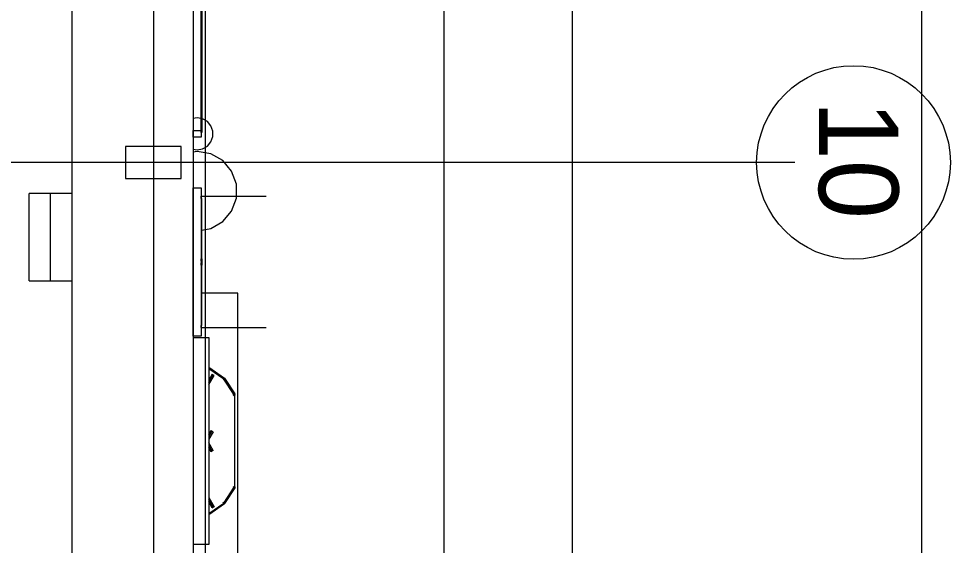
# Model space of a CAD drawing. Extents: x -264165 to -263575, y -1242333 to -1242036.
# Drawn here: x -263797.23 to -263785.53, y -1242144.69 to -1242138.07 of the extents above; entities that cross this region are included whole.
import ezdxf

# ---------------------------------------------------------------- set-up
doc = ezdxf.new("R2010")
doc.units = 0
doc.layers.add('KFA_HESCON_OSI_STAVBY', color=7, linetype='Continuous')
doc.layers.add('KFA_SITUACIA_DRS_VYTYCOVAK_SEDA', color=7, linetype='Continuous')

msp = doc.modelspace()

# ---------------------------------------------------------------- linework, layer by layer
at = {"layer": 'KFA_HESCON_OSI_STAVBY'}
for p, q in [((-263795.543, -1242080.447), (-263795.543, -1242248.737)), ((-263787.486, -1242139.882), (-263921.823, -1242139.882)), ((-263787.486, -1242139.882), (-263787.486, -1242139.882))]:
    msp.add_line(p, q, dxfattribs=at)
msp.add_circle((-263786.751, -1242139.882), 1.216, dxfattribs=at)
at = {"layer": 'KFA_SITUACIA_DRS_VYTYCOVAK_SEDA'}
for p, q in [((-263785.893, -1242228.625), (-263785.893, -1242090.308)), ((-263791.893, -1242228.625), (-263791.893, -1242100.14)), ((-263790.279, -1242228.625), (-263790.279, -1242100.14)), ((-263794.893, -1242101.382), (-263794.893, -1242227.382)), ((-263796.568, -1242132.882), (-263796.568, -1242139.882)), ((-263796.568, -1242132.882), (-263796.568, -1242139.882)), ((-263795.043, -1242132.882), (-263795.043, -1242139.882)), ((-263795.043, -1242132.882), (-263795.043, -1242139.882)), ((-263795.043, -1242137.469), (-263795.043, -1242139.482)), ((-263795.043, -1242137.469), (-263795.043, -1242139.482)), ((-263794.943, -1242139.505), (-263794.943, -1242137.469)), ((-263794.943, -1242139.505), (-263794.943, -1242137.469)), ((-263794.933, -1242137.446), (-263794.933, -1242139.505)), ((-263794.933, -1242137.446), (-263794.933, -1242139.505)), ((-263794.993, -1242139.322), (-263795.043, -1242139.331)), ((-263794.993, -1242139.322), (-263795.043, -1242139.331)), ((-263794.943, -1242139.331), (-263794.993, -1242139.322)), ((-263794.943, -1242139.331), (-263794.993, -1242139.322)), ((-263794.924, -1242139.334), (-263794.933, -1242139.333)), ((-263794.924, -1242139.334), (-263794.933, -1242139.333)), ((-263794.864, -1242139.369), (-263794.924, -1242139.334)), ((-263794.864, -1242139.369), (-263794.924, -1242139.334)), ((-263794.82, -1242139.422), (-263794.864, -1242139.369)), ((-263794.82, -1242139.422), (-263794.864, -1242139.369)), ((-263794.796, -1242139.487), (-263794.82, -1242139.422)), ((-263794.796, -1242139.487), (-263794.82, -1242139.422)), ((-263795.043, -1242139.562), (-263795.043, -1242139.482)), ((-263795.043, -1242139.562), (-263795.043, -1242139.482)), ((-263795.043, -1242139.482), (-263794.943, -1242139.482)), ((-263795.043, -1242139.482), (-263794.943, -1242139.482)), ((-263795.043, -1242139.562), (-263795.043, -1242139.582)), ((-263795.043, -1242139.562), (-263795.043, -1242139.582)), ((-263794.943, -1242139.562), (-263795.043, -1242139.562)), ((-263794.943, -1242139.562), (-263795.043, -1242139.562)), ((-263795.043, -1242139.582), (-263795.043, -1242140.182)), ((-263795.043, -1242139.582), (-263795.043, -1242140.182)), ((-263794.943, -1242139.482), (-263794.943, -1242139.562)), ((-263794.943, -1242139.482), (-263794.943, -1242139.562)), ((-263794.933, -1242139.505), (-263794.943, -1242139.505)), ((-263794.933, -1242139.505), (-263794.943, -1242139.505)), ((-263794.82, -1242139.622), (-263794.796, -1242139.557)), ((-263794.82, -1242139.622), (-263794.796, -1242139.557)), ((-263794.796, -1242139.557), (-263794.796, -1242139.487)), ((-263794.796, -1242139.557), (-263794.796, -1242139.487)), ((-263795.193, -1242139.682), (-263795.893, -1242139.682)), ((-263795.193, -1242139.682), (-263795.893, -1242139.682)), ((-263795.893, -1242139.682), (-263795.893, -1242139.882)), ((-263795.893, -1242139.682), (-263795.893, -1242139.882)), ((-263795.193, -1242139.882), (-263795.193, -1242139.682)), ((-263795.193, -1242139.882), (-263795.193, -1242139.682)), ((-263795.193, -1242139.882), (-263795.193, -1242139.682)), ((-263795.193, -1242139.882), (-263795.193, -1242139.682)), ((-263794.924, -1242139.71), (-263794.864, -1242139.675)), ((-263794.924, -1242139.71), (-263794.864, -1242139.675)), ((-263794.864, -1242139.675), (-263794.82, -1242139.622)), ((-263794.864, -1242139.675), (-263794.82, -1242139.622)), ((-263795.043, -1242139.713), (-263794.993, -1242139.722)), ((-263795.043, -1242139.713), (-263794.993, -1242139.722)), ((-263794.993, -1242139.742), (-263795.043, -1242139.751)), ((-263794.993, -1242139.742), (-263795.043, -1242139.751)), ((-263794.993, -1242139.722), (-263794.924, -1242139.71)), ((-263794.993, -1242139.722), (-263794.924, -1242139.71)), ((-263794.822, -1242139.772), (-263794.993, -1242139.742)), ((-263794.822, -1242139.772), (-263794.993, -1242139.742)), ((-263794.671, -1242139.859), (-263794.822, -1242139.772)), ((-263794.671, -1242139.859), (-263794.822, -1242139.772)), ((-263796.568, -1242139.882), (-263796.568, -1242146.882)), ((-263796.568, -1242139.882), (-263796.568, -1242146.882)), ((-263795.893, -1242139.882), (-263795.893, -1242140.082)), ((-263795.893, -1242139.882), (-263795.893, -1242140.082)), ((-263795.193, -1242140.082), (-263795.193, -1242139.882)), ((-263795.193, -1242140.082), (-263795.193, -1242139.882)), ((-263795.193, -1242140.082), (-263795.193, -1242139.882)), ((-263795.193, -1242140.082), (-263795.193, -1242139.882)), ((-263795.043, -1242139.882), (-263795.043, -1242146.882)), ((-263795.043, -1242139.882), (-263795.043, -1242146.882)), ((-263794.56, -1242139.992), (-263794.671, -1242139.859)), ((-263794.56, -1242139.992), (-263794.671, -1242139.859)), ((-263794.5, -1242140.155), (-263794.56, -1242139.992)), ((-263794.5, -1242140.155), (-263794.56, -1242139.992)), ((-263795.893, -1242140.082), (-263795.193, -1242140.082)), ((-263795.893, -1242140.082), (-263795.193, -1242140.082)), ((-263794.5, -1242140.329), (-263794.5, -1242140.155)), ((-263794.5, -1242140.329), (-263794.5, -1242140.155)), ((-263797.101, -1242141.369), (-263797.101, -1242140.27)), ((-263797.101, -1242141.369), (-263797.101, -1242140.27)), ((-263796.834, -1242140.27), (-263797.101, -1242140.27)), ((-263796.834, -1242140.27), (-263797.101, -1242140.27)), ((-263796.834, -1242141.369), (-263796.834, -1242140.27)), ((-263796.834, -1242141.369), (-263796.834, -1242140.27)), ((-263796.568, -1242140.27), (-263796.834, -1242140.27)), ((-263796.568, -1242140.27), (-263796.834, -1242140.27)), ((-263795.043, -1242140.182), (-263795.043, -1242140.202)), ((-263795.043, -1242140.182), (-263795.043, -1242140.202)), ((-263795.043, -1242142.062), (-263795.043, -1242140.202)), ((-263795.043, -1242142.062), (-263795.043, -1242140.202)), ((-263795.043, -1242140.202), (-263794.943, -1242140.202)), ((-263795.043, -1242140.202), (-263794.943, -1242140.202)), ((-263794.943, -1242140.202), (-263794.943, -1242142.062)), ((-263794.943, -1242140.202), (-263794.943, -1242142.062)), ((-263794.943, -1242140.307), (-263794.128, -1242140.307)), ((-263794.943, -1242140.307), (-263794.128, -1242140.307)), ((-263794.943, -1242140.333), (-263794.943, -1242140.307)), ((-263794.943, -1242140.333), (-263794.943, -1242140.307)), ((-263794.943, -1242140.333), (-263794.933, -1242140.333)), ((-263794.943, -1242140.333), (-263794.933, -1242140.333)), ((-263794.933, -1242141.092), (-263794.933, -1242140.333)), ((-263794.933, -1242141.092), (-263794.933, -1242140.333)), ((-263794.56, -1242140.492), (-263794.5, -1242140.329)), ((-263794.56, -1242140.492), (-263794.5, -1242140.329)), ((-263794.671, -1242140.625), (-263794.56, -1242140.492)), ((-263794.671, -1242140.625), (-263794.56, -1242140.492)), ((-263794.822, -1242140.712), (-263794.671, -1242140.625)), ((-263794.822, -1242140.712), (-263794.671, -1242140.625)), ((-263794.933, -1242140.732), (-263794.822, -1242140.712)), ((-263794.933, -1242140.732), (-263794.822, -1242140.712)), ((-263794.943, -1242141.092), (-263794.933, -1242141.092)), ((-263794.943, -1242141.092), (-263794.933, -1242141.092)), ((-263794.943, -1242141.122), (-263794.943, -1242141.092)), ((-263794.943, -1242141.122), (-263794.943, -1242141.092)), ((-263794.943, -1242141.092), (-263794.933, -1242141.092)), ((-263794.943, -1242141.092), (-263794.933, -1242141.092)), ((-263794.933, -1242141.092), (-263794.933, -1242141.172)), ((-263794.933, -1242141.092), (-263794.933, -1242141.172)), ((-263794.943, -1242141.173), (-263794.943, -1242141.142)), ((-263794.943, -1242141.173), (-263794.943, -1242141.142)), ((-263794.933, -1242141.172), (-263794.943, -1242141.172)), ((-263794.933, -1242141.172), (-263794.943, -1242141.172)), ((-263794.933, -1242141.173), (-263794.943, -1242141.173)), ((-263794.933, -1242141.173), (-263794.943, -1242141.173)), ((-263794.933, -1242141.932), (-263794.933, -1242141.173)), ((-263794.933, -1242141.932), (-263794.933, -1242141.173)), ((-263797.101, -1242141.369), (-263796.834, -1242141.369)), ((-263797.101, -1242141.369), (-263796.834, -1242141.369)), ((-263796.834, -1242141.369), (-263796.568, -1242141.369)), ((-263796.834, -1242141.369), (-263796.568, -1242141.369)), ((-263794.482, -1242141.522), (-263794.933, -1242141.522)), ((-263794.482, -1242141.522), (-263794.933, -1242141.522)), ((-263794.482, -1242145.242), (-263794.482, -1242141.522)), ((-263794.482, -1242145.242), (-263794.482, -1242141.522)), ((-263794.943, -1242141.957), (-263794.943, -1242141.932)), ((-263794.943, -1242141.957), (-263794.943, -1242141.932)), ((-263794.933, -1242141.932), (-263794.943, -1242141.932)), ((-263794.933, -1242141.932), (-263794.943, -1242141.932)), ((-263794.943, -1242141.957), (-263794.128, -1242141.957)), ((-263794.943, -1242141.957), (-263794.128, -1242141.957)), ((-263795.043, -1242142.062), (-263795.043, -1242142.082)), ((-263795.043, -1242142.062), (-263795.043, -1242142.082)), ((-263794.943, -1242142.062), (-263795.043, -1242142.062)), ((-263794.943, -1242142.062), (-263795.043, -1242142.062)), ((-263795.043, -1242142.082), (-263794.847, -1242142.082)), ((-263795.043, -1242142.082), (-263794.847, -1242142.082)), ((-263794.847, -1242142.082), (-263794.847, -1242144.682)), ((-263794.847, -1242142.082), (-263794.847, -1242144.682)), ((-263794.847, -1242142.454), (-263794.649, -1242142.59)), ((-263794.847, -1242142.454), (-263794.649, -1242142.59)), ((-263794.656, -1242142.597), (-263794.847, -1242142.467)), ((-263794.656, -1242142.597), (-263794.847, -1242142.467)), ((-263794.656, -1242142.603), (-263794.847, -1242142.473)), ((-263794.656, -1242142.603), (-263794.847, -1242142.473)), ((-263794.847, -1242142.477), (-263794.842, -1242142.476)), ((-263794.847, -1242142.477), (-263794.842, -1242142.476)), ((-263794.842, -1242142.476), (-263794.842, -1242142.476)), ((-263794.842, -1242142.476), (-263794.842, -1242142.476)), ((-263794.804, -1242142.543), (-263794.847, -1242142.617)), ((-263794.804, -1242142.543), (-263794.847, -1242142.617)), ((-263794.847, -1242142.651), (-263794.789, -1242142.552)), ((-263794.847, -1242142.651), (-263794.789, -1242142.552)), ((-263794.847, -1242142.672), (-263794.78, -1242142.557)), ((-263794.847, -1242142.672), (-263794.78, -1242142.557)), ((-263794.804, -1242142.543), (-263794.789, -1242142.552)), ((-263794.804, -1242142.543), (-263794.789, -1242142.552)), ((-263794.78, -1242142.557), (-263794.789, -1242142.552)), ((-263794.78, -1242142.557), (-263794.789, -1242142.552)), ((-263794.664, -1242142.6), (-263794.666, -1242142.603)), ((-263794.664, -1242142.6), (-263794.666, -1242142.603)), ((-263794.666, -1242142.603), (-263794.659, -1242142.613)), ((-263794.666, -1242142.603), (-263794.659, -1242142.613)), ((-263794.664, -1242142.597), (-263794.664, -1242142.603)), ((-263794.664, -1242142.597), (-263794.664, -1242142.603)), ((-263794.654, -1242142.606), (-263794.664, -1242142.603)), ((-263794.654, -1242142.606), (-263794.664, -1242142.603)), ((-263794.659, -1242142.613), (-263794.651, -1242142.61)), ((-263794.659, -1242142.613), (-263794.651, -1242142.61)), ((-263794.528, -1242142.795), (-263794.656, -1242142.597)), ((-263794.528, -1242142.795), (-263794.656, -1242142.597)), ((-263794.528, -1242142.801), (-263794.656, -1242142.603)), ((-263794.528, -1242142.801), (-263794.656, -1242142.603)), ((-263794.649, -1242142.59), (-263794.52, -1242142.79)), ((-263794.649, -1242142.59), (-263794.52, -1242142.79)), ((-263794.536, -1242142.798), (-263794.539, -1242142.801)), ((-263794.536, -1242142.798), (-263794.539, -1242142.801)), ((-263794.539, -1242142.801), (-263794.532, -1242142.81)), ((-263794.539, -1242142.801), (-263794.532, -1242142.81)), ((-263794.536, -1242142.801), (-263794.536, -1242142.789)), ((-263794.536, -1242142.801), (-263794.536, -1242142.789)), ((-263794.536, -1242142.789), (-263794.536, -1242142.789)), ((-263794.536, -1242142.789), (-263794.536, -1242142.789)), ((-263794.525, -1242142.805), (-263794.536, -1242142.801)), ((-263794.525, -1242142.805), (-263794.536, -1242142.801)), ((-263794.532, -1242142.81), (-263794.52, -1242142.807)), ((-263794.532, -1242142.81), (-263794.52, -1242142.807)), ((-263794.52, -1242142.79), (-263794.528, -1242142.795)), ((-263794.52, -1242142.79), (-263794.528, -1242142.795)), ((-263794.52, -1242142.795), (-263794.528, -1242142.801)), ((-263794.52, -1242142.795), (-263794.528, -1242142.801)), ((-263794.518, -1242142.795), (-263794.525, -1242142.805)), ((-263794.518, -1242142.795), (-263794.525, -1242142.805)), ((-263794.522, -1242142.791), (-263794.52, -1242142.795)), ((-263794.522, -1242142.791), (-263794.52, -1242142.795)), ((-263794.518, -1242142.795), (-263794.521, -1242142.791)), ((-263794.518, -1242142.795), (-263794.521, -1242142.791)), ((-263794.52, -1242142.793), (-263794.52, -1242142.79)), ((-263794.52, -1242142.793), (-263794.52, -1242142.79)), ((-263794.52, -1242143.962), (-263794.52, -1242142.798)), ((-263794.52, -1242143.962), (-263794.52, -1242142.798)), ((-263794.52, -1242142.807), (-263794.52, -1242142.798)), ((-263794.52, -1242142.807), (-263794.52, -1242142.798)), ((-263794.52, -1242142.798), (-263794.52, -1242142.807)), ((-263794.52, -1242142.798), (-263794.52, -1242142.807)), ((-263794.52, -1242142.798), (-263794.52, -1242142.807)), ((-263794.52, -1242142.798), (-263794.52, -1242142.807)), ((-263794.847, -1242143.303), (-263794.817, -1242143.251)), ((-263794.847, -1242143.303), (-263794.817, -1242143.251)), ((-263794.817, -1242143.251), (-263794.847, -1242143.303)), ((-263794.817, -1242143.251), (-263794.847, -1242143.303)), ((-263794.807, -1242143.256), (-263794.847, -1242143.324)), ((-263794.807, -1242143.256), (-263794.847, -1242143.324)), ((-263794.793, -1242143.264), (-263794.847, -1242143.358)), ((-263794.793, -1242143.264), (-263794.847, -1242143.358)), ((-263794.817, -1242143.251), (-263794.807, -1242143.256)), ((-263794.817, -1242143.251), (-263794.807, -1242143.256)), ((-263794.807, -1242143.256), (-263794.817, -1242143.251)), ((-263794.807, -1242143.256), (-263794.817, -1242143.251)), ((-263794.793, -1242143.264), (-263794.807, -1242143.256)), ((-263794.793, -1242143.264), (-263794.807, -1242143.256)), ((-263794.793, -1242143.264), (-263794.807, -1242143.256)), ((-263794.793, -1242143.264), (-263794.807, -1242143.256)), ((-263794.793, -1242143.499), (-263794.847, -1242143.406)), ((-263794.793, -1242143.499), (-263794.847, -1242143.406)), ((-263794.847, -1242143.44), (-263794.807, -1242143.508)), ((-263794.847, -1242143.44), (-263794.807, -1242143.508)), ((-263794.847, -1242143.461), (-263794.817, -1242143.513)), ((-263794.847, -1242143.461), (-263794.817, -1242143.513)), ((-263794.817, -1242143.513), (-263794.847, -1242143.461)), ((-263794.817, -1242143.513), (-263794.847, -1242143.461)), ((-263794.817, -1242143.513), (-263794.807, -1242143.508)), ((-263794.817, -1242143.513), (-263794.807, -1242143.508)), ((-263794.807, -1242143.508), (-263794.817, -1242143.513)), ((-263794.807, -1242143.508), (-263794.817, -1242143.513)), ((-263794.793, -1242143.499), (-263794.807, -1242143.508)), ((-263794.793, -1242143.499), (-263794.807, -1242143.508)), ((-263794.793, -1242143.499), (-263794.807, -1242143.508)), ((-263794.793, -1242143.499), (-263794.807, -1242143.508)), ((-263794.656, -1242144.161), (-263794.529, -1242143.963)), ((-263794.656, -1242144.161), (-263794.529, -1242143.963)), ((-263794.52, -1242143.968), (-263794.649, -1242144.168)), ((-263794.52, -1242143.968), (-263794.649, -1242144.168)), ((-263794.648, -1242144.168), (-263794.52, -1242143.968)), ((-263794.648, -1242144.168), (-263794.52, -1242143.968)), ((-263794.539, -1242143.963), (-263794.532, -1242143.953)), ((-263794.539, -1242143.963), (-263794.532, -1242143.953)), ((-263794.533, -1242143.97), (-263794.539, -1242143.963)), ((-263794.533, -1242143.97), (-263794.539, -1242143.963)), ((-263794.532, -1242143.953), (-263794.52, -1242143.957)), ((-263794.532, -1242143.953), (-263794.52, -1242143.957)), ((-263794.532, -1242143.953), (-263794.52, -1242143.957)), ((-263794.532, -1242143.953), (-263794.52, -1242143.957)), ((-263794.532, -1242143.953), (-263794.532, -1242143.953)), ((-263794.532, -1242143.953), (-263794.532, -1242143.953)), ((-263794.529, -1242143.963), (-263794.52, -1242143.968)), ((-263794.529, -1242143.963), (-263794.52, -1242143.968)), ((-263794.52, -1242143.968), (-263794.528, -1242143.963)), ((-263794.52, -1242143.968), (-263794.528, -1242143.963)), ((-263794.52, -1242143.957), (-263794.52, -1242143.968)), ((-263794.52, -1242143.957), (-263794.52, -1242143.968)), ((-263794.52, -1242143.968), (-263794.52, -1242143.957)), ((-263794.52, -1242143.968), (-263794.52, -1242143.957)), ((-263794.52, -1242143.968), (-263794.52, -1242143.957)), ((-263794.52, -1242143.968), (-263794.52, -1242143.957)), ((-263794.52, -1242143.968), (-263794.52, -1242143.957)), ((-263794.52, -1242143.968), (-263794.52, -1242143.957)), ((-263794.52, -1242143.957), (-263794.52, -1242143.968)), ((-263794.52, -1242143.957), (-263794.52, -1242143.968)), ((-263794.52, -1242143.968), (-263794.52, -1242143.962)), ((-263794.52, -1242143.968), (-263794.52, -1242143.962)), ((-263794.52, -1242143.962), (-263794.52, -1242143.962)), ((-263794.52, -1242143.962), (-263794.52, -1242143.962)), ((-263794.847, -1242144.091), (-263794.78, -1242144.206)), ((-263794.847, -1242144.091), (-263794.78, -1242144.206)), ((-263794.789, -1242144.212), (-263794.847, -1242144.112)), ((-263794.789, -1242144.212), (-263794.847, -1242144.112)), ((-263794.804, -1242144.22), (-263794.847, -1242144.147)), ((-263794.804, -1242144.22), (-263794.847, -1242144.147)), ((-263794.666, -1242144.161), (-263794.659, -1242144.151)), ((-263794.666, -1242144.161), (-263794.659, -1242144.151)), ((-263794.659, -1242144.151), (-263794.651, -1242144.154)), ((-263794.659, -1242144.151), (-263794.651, -1242144.154)), ((-263794.659, -1242144.151), (-263794.651, -1242144.154)), ((-263794.659, -1242144.151), (-263794.651, -1242144.154)), ((-263794.659, -1242144.151), (-263794.659, -1242144.151)), ((-263794.659, -1242144.151), (-263794.659, -1242144.151)), ((-263794.847, -1242144.291), (-263794.656, -1242144.161)), ((-263794.847, -1242144.291), (-263794.656, -1242144.161)), ((-263794.649, -1242144.168), (-263794.847, -1242144.303)), ((-263794.649, -1242144.168), (-263794.847, -1242144.303)), ((-263794.847, -1242144.303), (-263794.648, -1242144.168)), ((-263794.847, -1242144.303), (-263794.648, -1242144.168)), ((-263794.804, -1242144.22), (-263794.789, -1242144.212)), ((-263794.804, -1242144.22), (-263794.789, -1242144.212)), ((-263794.78, -1242144.206), (-263794.789, -1242144.212)), ((-263794.78, -1242144.206), (-263794.789, -1242144.212)), ((-263794.666, -1242144.161), (-263794.663, -1242144.165)), ((-263794.666, -1242144.161), (-263794.663, -1242144.165)), ((-263794.847, -1242144.286), (-263794.843, -1242144.288)), ((-263794.847, -1242144.286), (-263794.843, -1242144.288)), ((-263794.847, -1242144.286), (-263794.842, -1242144.288)), ((-263794.847, -1242144.286), (-263794.842, -1242144.288)), ((-263794.843, -1242144.288), (-263794.843, -1242144.288)), ((-263794.843, -1242144.288), (-263794.843, -1242144.288)), ((-263794.842, -1242144.288), (-263794.842, -1242144.288)), ((-263794.842, -1242144.288), (-263794.842, -1242144.288)), ((-263795.043, -1242144.682), (-263795.043, -1242144.702)), ((-263795.043, -1242144.682), (-263795.043, -1242144.702)), ((-263794.847, -1242144.682), (-263795.043, -1242144.682)), ((-263794.847, -1242144.682), (-263795.043, -1242144.682))]:
    msp.add_line(p, q, dxfattribs=at)

# ---------------------------------------------------------------- texts
at = {"layer": 'KFA_HESCON_OSI_STAVBY'}
msp.add_text('10', height=1, rotation=270, dxfattribs=at).set_placement((-263787.186, -1242139.105))

doc.saveas('drawing.dxf')
